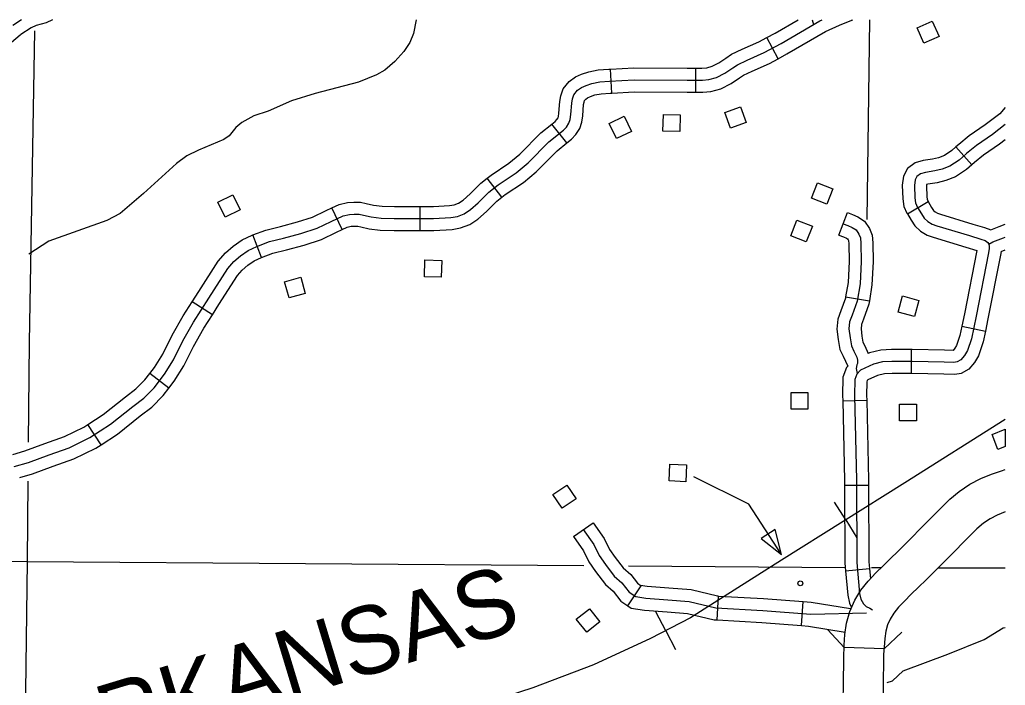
# Model space of a CAD drawing. Extents: x 1370130 to 1380143, y 377636 to 380256.
# Drawn here: x 1378779.4 to 1379037.7, y 378658.4 to 378832.9 of the extents above; entities that cross this region are included whole.
import ezdxf

# ---------------------------------------------------------------- set-up
doc = ezdxf.new("R2010")
doc.units = 0
for name, color, linetype in [('Level 10', 7, 'Continuous'), ('Level 32', 7, 'Continuous'), ('Level 35', 7, 'Continuous'), ('Level 37', 7, 'Continuous'), ('Level 40', 7, 'Continuous'), ('Level 45', 7, 'Continuous'), ('Level 5', 7, 'Continuous'), ('Level 56', 7, 'Continuous')]:
    doc.layers.add(name, color=color, linetype=linetype)

msp = doc.modelspace()

# ---------------------------------------------------------------- linework, layer by layer
at = {"layer": 'Level 10'}
msp.add_line((1379005.93, 378667.96), (1378995.44, 378668.29), dxfattribs=at)
for points in [[(1378995.44, 378668.29), (1378995.46, 378668.91), (1378995.64, 378671.72), (1378996.07, 378674.7), (1378996.92, 378677.76), (1378998.21, 378680.65), (1378999.83, 378683.29), (1379001.73, 378685.71), (1379003.74, 378687.82), (1379005.68, 378689.72), (1379007.61, 378691.6), (1379009.52, 378693.46), (1379011.41, 378695.37), (1379013.33, 378697.28), (1379015.2, 378699.19), (1379017.12, 378701.13), (1379019.05, 378703.09), (1379021.03, 378705.08), (1379023.14, 378707.15), (1379025.58, 378709.23), (1379028.34, 378711.11), (1379031.25, 378712.58), (1379034.07, 378713.7), (1379036.71, 378714.63), (1379037.67, 378714.97)], [(1379037.67, 378703.83), (1379035.58, 378703), (1379033.68, 378702.04), (1379031.96, 378700.88), (1379030.24, 378699.4), (1379028.42, 378697.62), (1379026.51, 378695.7), (1379024.59, 378693.75), (1379022.68, 378691.82), (1379020.78, 378689.88), (1379018.84, 378687.96), (1379016.91, 378686.01), (1379014.94, 378684.08), (1379013.03, 378682.22), (1379011.21, 378680.44), (1379009.67, 378678.83), (1379008.47, 378677.29), (1379007.52, 378675.74), (1379006.82, 378674.19), (1379006.37, 378672.55), (1379006.1, 378670.63), (1379005.95, 378668.4), (1379005.93, 378667.96)], [(1378995.01, 378646.07), (1378995.06, 378649.05), (1378995.1, 378652.05), (1378995.16, 378655.03), (1378995.23, 378657.94), (1378995.29, 378660.75), (1378995.33, 378663.5), (1378995.37, 378666.21), (1378995.44, 378668.29)], [(1379005.51, 378645.9), (1379005.55, 378648.88), (1379005.6, 378651.86), (1379005.66, 378654.8), (1379005.73, 378657.7), (1379005.79, 378660.56), (1379005.83, 378663.34), (1379005.87, 378665.96), (1379005.93, 378667.96)]]:
    msp.add_lwpolyline(points, dxfattribs=at)
at = {"layer": 'Level 32'}
for p, q in [((1378997.44, 378832.8), (1378997.4, 378832.91)), ((1378978.16, 378822.69), (1378975.18, 378828.24)), ((1378934.51, 378813.69), (1378934.19, 378819.98)), ((1378956.52, 378813.93), (1378956.52, 378820.23)), ((1378922.74, 378800.59), (1378918.78, 378805.49)), ((1379024.73, 378799.54), (1379028.94, 378794.85)), ((1378905.75, 378786.38), (1378901.86, 378791.34)), ((1379012.01, 378782.02), (1379017.42, 378785.26)), ((1378863.83, 378777.87), (1378861.16, 378783.58)), ((1378884.35, 378777.66), (1378884.35, 378783.96)), ((1378994.07, 378776.44), (1378996.33, 378782.32)), ((1378842.72, 378770.57), (1378840.48, 378776.46)), ((1378829.86, 378755.55), (1378824.56, 378758.95)), ((1378995.83, 378760.22), (1379002.05, 378759.2)), ((1379026.28, 378752.57), (1379032.44, 378751.26)), ((1379013.01, 378746.44), (1379013.01, 378740.14)), ((1378818.43, 378736.27), (1378813.45, 378740.12)), ((1378995.05, 378732.95), (1379001.35, 378733.1)), ((1378800.7, 378721.46), (1378797.24, 378726.73)), ((1378995.55, 378710.84), (1379001.85, 378710.86)), ((1378924.47, 378697.39), (1378929.62, 378701.01)), ((1378995.79, 378688.4), (1379002.07, 378688.97)), ((1378938.76, 378679.23), (1378942.25, 378684.47)), ((1378962.18, 378675.49), (1378962.52, 378681.78)), ((1378984.23, 378674.04), (1378984.72, 378680.32))]:
    msp.add_line(p, q, dxfattribs=at)
for points in [[(1378777.92, 378715.7), (1378781.69, 378716.82), (1378787.05, 378718.81), (1378792.34, 378720.66), (1378797.76, 378723.31), (1378803.12, 378726.82), (1378809.01, 378731.52), (1378811.92, 378733.7), (1378814.56, 378736.41), (1378817.27, 378739.92), (1378819.66, 378743.69), (1378822.1, 378748.72), (1378824.88, 378753.62), (1378828.91, 378759.9), (1378833.87, 378767.71), (1378835.46, 378769.5), (1378837.25, 378771.02), (1378839.23, 378772.41), (1378841.48, 378773.47), (1378844.79, 378774.73), (1378848.49, 378775.65), (1378853.05, 378776.84), (1378857.29, 378778.23), (1378860.99, 378780.02), (1378864.1, 378781.48), (1378865.75, 378781.87), (1378867.01, 378781.94), (1378868.33, 378781.94), (1378869.46, 378781.68), (1378871.51, 378781.21), (1378874.09, 378780.88), (1378877.53, 378780.81), (1378887.84, 378780.81), (1378892.34, 378781.01), (1378894.06, 378781.34), (1378895.85, 378782.01), (1378897.5, 378783.13), (1378899.55, 378784.92), (1378902.33, 378787.7), (1378904.77, 378789.62), (1378909.47, 378792.73), (1378912.58, 378795.37), (1378918.07, 378800.87), (1378921.84, 378803.91), (1378922.63, 378804.77), (1378923.29, 378805.76), (1378923.62, 378806.76), (1378923.82, 378808.08), (1378924.02, 378811.06), (1378924.22, 378812.12), (1378924.61, 378813.24), (1378925.54, 378814.43), (1378926.6, 378815.16), (1378927.79, 378815.69), (1378929.31, 378816.22), (1378931.36, 378816.62), (1378933.94, 378816.81), (1378940.36, 378817.14), (1378954.31, 378817.08), (1378958.28, 378817.08), (1378960, 378817.21), (1378961.98, 378817.74), (1378964.17, 378818.87), (1378966.22, 378820.25), (1378967.47, 378821.12), (1378969.99, 378822.31), (1378974.48, 378824.29), (1378978.91, 378826.67), (1378989.1, 378832.63), (1378989.71, 378832.91)], [(1378975.18, 378828.24), (1378977.37, 378829.42), (1378983.35, 378832.91)], [(1378978.16, 378822.69), (1378980.45, 378823.93), (1378990.56, 378829.84), (1378994.18, 378831.52), (1378997.44, 378832.8)], [(1378987.03, 378832.91), (1378987.39, 378831.63)], [(1378997.44, 378832.8), (1378997.72, 378832.91)], [(1378956.52, 378820.23), (1378958.16, 378820.23), (1378959.47, 378820.33), (1378960.84, 378820.7), (1378962.55, 378821.58), (1378964.44, 378822.86), (1378965.9, 378823.85), (1378968.67, 378825.17), (1378973.1, 378827.12), (1378975.18, 378828.24)], [(1378956.52, 378813.93), (1378958.4, 378813.93), (1378960.53, 378814.09), (1378963.12, 378814.78), (1378965.78, 378816.15), (1378967.99, 378817.65), (1378969.05, 378818.38), (1378971.3, 378819.44), (1378975.87, 378821.46), (1378978.16, 378822.69)], [(1378918.78, 378805.49), (1378919.68, 378806.22), (1378920.15, 378806.72), (1378920.44, 378807.16), (1378920.55, 378807.49), (1378920.69, 378808.42), (1378920.89, 378811.45), (1378921.17, 378812.93), (1378921.81, 378814.77), (1378923.35, 378816.75), (1378925.05, 378817.92), (1378926.63, 378818.62), (1378928.49, 378819.27), (1378930.94, 378819.74), (1378933.74, 378819.96), (1378934.19, 378819.98)], [(1378934.19, 378819.98), (1378940.28, 378820.3), (1378954.32, 378820.23), (1378956.52, 378820.23)], [(1378922.74, 378800.59), (1378924, 378801.6), (1378925.11, 378802.82), (1378926.15, 378804.37), (1378926.7, 378806.02), (1378926.96, 378807.74), (1378927.15, 378810.66), (1378927.27, 378811.3), (1378927.42, 378811.71), (1378927.73, 378812.11), (1378928.14, 378812.4), (1378928.95, 378812.76), (1378930.13, 378813.17), (1378931.78, 378813.49), (1378934.14, 378813.67), (1378934.51, 378813.69)], [(1378934.51, 378813.69), (1378940.43, 378813.99), (1378954.3, 378813.93), (1378956.52, 378813.93)], [(1379037.67, 378809.9), (1379036.21, 378808.27), (1379032.42, 378805.33), (1379028.22, 378802.46), (1379025.48, 378800.21), (1379024.73, 378799.54)], [(1378901.86, 378791.34), (1378902.93, 378792.17), (1378907.57, 378795.25), (1378910.44, 378797.69), (1378915.96, 378803.21), (1378918.78, 378805.49)], [(1379037.67, 378805.42), (1379034.28, 378802.78), (1379030.11, 378799.94), (1379027.53, 378797.82), (1379025.61, 378796.1), (1379023.17, 378794.51), (1379021.12, 378793.72), (1379019.2, 378793.26), (1379016.75, 378792.86), (1379015.43, 378792.53), (1379014.5, 378791.8), (1379014.04, 378790.94), (1379013.84, 378789.42), (1379013.97, 378786.24), (1379014.17, 378784.85), (1379014.7, 378783.66), (1379015.69, 378782.01), (1379016.42, 378780.88), (1379017.35, 378780.02), (1379018.54, 378779.29), (1379019.73, 378778.9), (1379028.26, 378776.32), (1379031.23, 378775.39), (1379032.36, 378774.99), (1379033.07, 378774.53), (1379033.39, 378774.07), (1379033.48, 378773.4), (1379033.48, 378772.87), (1379033.29, 378771.75), (1379030.04, 378755.14), (1379028.79, 378749.25), (1379027.8, 378746.14), (1379027, 378744.88), (1379026.01, 378743.69), (1379025.08, 378743.16), (1379024.22, 378743.03), (1379021.64, 378743.1), (1379013.25, 378743.29), (1379007.95, 378743.29), (1379005.51, 378743.16), (1379003.13, 378742.57), (1378999.75, 378741.04), (1378998.76, 378739.99), (1378998.23, 378738.6), (1378998.17, 378734.36), (1378998.7, 378712.13), (1378998.76, 378690.55), (1378999.49, 378682.48), (1378999.82, 378680.96), (1379000.48, 378679.7), (1379001.21, 378679.04), (1379002.2, 378678.58), (1379002.85, 378678.17)], [(1378905.75, 378786.38), (1378906.62, 378787.06), (1378911.37, 378790.2), (1378914.72, 378793.06), (1378920.18, 378798.52), (1378922.74, 378800.59)], [(1379037.67, 378801.43), (1379036.13, 378800.24), (1379032, 378797.42), (1379029.58, 378795.43), (1379028.94, 378794.85)], [(1379024.73, 378799.54), (1379023.69, 378798.61), (1379021.72, 378797.33), (1379020.17, 378796.73), (1379018.57, 378796.35), (1379016.12, 378795.95), (1379014.01, 378795.42), (1379012.04, 378793.87), (1379010.99, 378791.92), (1379010.68, 378789.56), (1379010.83, 378785.95), (1379011.11, 378783.97), (1379011.9, 378782.21), (1379012.01, 378782.02)], [(1379028.94, 378794.85), (1379027.53, 378793.59), (1379024.61, 378791.69), (1379022.06, 378790.71), (1379019.82, 378790.17), (1379017.39, 378789.77), (1379017.05, 378789.69), (1379017, 378789.28), (1379017.11, 378786.53), (1379017.23, 378785.73), (1379017.5, 378785.12), (1379017.42, 378785.26)], [(1378884.35, 378783.96), (1378887.77, 378783.96), (1378891.97, 378784.15), (1378893.21, 378784.39), (1378894.39, 378784.83), (1378895.57, 378785.63), (1378897.4, 378787.22), (1378900.23, 378790.06), (1378901.86, 378791.34)], [(1378861.16, 378783.58), (1378863.05, 378784.46), (1378865.3, 378785), (1378866.93, 378785.09), (1378868.7, 378785.09), (1378870.16, 378784.74), (1378872.06, 378784.32), (1378874.32, 378784.03), (1378877.56, 378783.96), (1378884.35, 378783.96)], [(1378884.35, 378777.66), (1378887.91, 378777.66), (1378892.71, 378777.88), (1378894.91, 378778.3), (1378897.3, 378779.19), (1378899.43, 378780.63), (1378901.7, 378782.61), (1378904.42, 378785.34), (1378905.75, 378786.38)], [(1379017.42, 378785.26), (1379018.37, 378783.67), (1379018.85, 378782.92), (1379019.26, 378782.54), (1379019.87, 378782.17), (1379020.68, 378781.9), (1379029.18, 378779.33), (1379032.23, 378778.38), (1379033.84, 378777.81)], [(1378840.48, 378776.46), (1378843.84, 378777.74), (1378847.71, 378778.71), (1378852.16, 378779.87), (1378856.11, 378781.16), (1378859.64, 378782.87), (1378861.16, 378783.58)], [(1378996.33, 378782.32), (1378997.58, 378781.84), (1378999, 378781.25), (1379000.81, 378780.09), (1379002.11, 378778.14), (1379002.79, 378776.43), (1379002.92, 378774.37), (1379003.02, 378769.43), (1379002.73, 378763.35), (1379002.05, 378759.2)], [(1379012.01, 378782.02), (1379013.02, 378780.34), (1379013.99, 378778.84), (1379015.43, 378777.5), (1379017.2, 378776.42), (1379018.77, 378775.89), (1379027.33, 378773.3), (1379030.2, 378772.41)], [(1378995.2, 378779.38), (1378996.41, 378778.91), (1378997.53, 378778.44), (1378998.56, 378777.79), (1378999.31, 378776.67), (1378999.68, 378775.73), (1378999.77, 378774.24), (1378999.87, 378769.47), (1378999.59, 378763.68), (1378998.84, 378759.1), (1378997.53, 378755.46), (1378996.88, 378753.68), (1378996.69, 378751.81), (1378996.97, 378749.48), (1378997.35, 378747.42), (1378998, 378746.02), (1378998.75, 378744.43), (1378998.93, 378743.59), (1378998.93, 378742.75), (1378998.75, 378742.38), (1378998.56, 378741.44), (1378998.87, 378740.1)], [(1379033.84, 378777.81), (1379036.09, 378778.7), (1379037.67, 378779.27)], [(1378842.72, 378770.57), (1378845.73, 378771.72), (1378849.27, 378772.6), (1378853.94, 378773.82), (1378858.47, 378775.31), (1378862.34, 378777.18), (1378863.83, 378777.87)], [(1378863.83, 378777.87), (1378865.15, 378778.49), (1378866.21, 378778.74), (1378867.09, 378778.79), (1378867.97, 378778.79), (1378868.75, 378778.61), (1378870.96, 378778.11), (1378873.85, 378777.74), (1378877.49, 378777.66), (1378884.35, 378777.66)], [(1378824.56, 378758.95), (1378826.26, 378761.6), (1378831.35, 378769.62), (1378833.25, 378771.75), (1378835.32, 378773.52), (1378837.65, 378775.15), (1378840.25, 378776.37), (1378840.48, 378776.46)], [(1378994.07, 378776.44), (1378995.24, 378775.99), (1378996.07, 378775.64), (1378996.31, 378775.49), (1378996.5, 378775.19), (1378996.57, 378775.03), (1378996.63, 378774.11), (1378996.72, 378769.52), (1378996.45, 378764.01), (1378995.83, 378760.22)], [(1379033.39, 378774.07), (1379034.42, 378774.66), (1379037.2, 378775.75), (1379037.67, 378775.92)], [(1379030.2, 378772.41), (1379026.96, 378755.77), (1379026.28, 378752.57)], [(1379036.55, 378772.11), (1379036.38, 378771.17), (1379033.13, 378754.51), (1379032.44, 378751.26)], [(1379036.55, 378772.11), (1379037.67, 378772.55)], [(1378829.86, 378755.55), (1378831.57, 378758.21), (1378836.4, 378765.81), (1378837.67, 378767.24), (1378839.18, 378768.53), (1378840.82, 378769.68), (1378842.71, 378770.57), (1378842.72, 378770.57)], [(1378813.45, 378740.12), (1378814.69, 378741.73), (1378816.9, 378745.23), (1378819.31, 378750.19), (1378822.18, 378755.25), (1378824.56, 378758.95)], [(1378995.83, 378760.22), (1378995.78, 378759.89), (1378994.57, 378756.53), (1378993.79, 378754.4), (1378993.52, 378751.78), (1378993.86, 378749.01), (1378994.32, 378746.46), (1378995.15, 378744.68), (1378996.38, 378742.06)], [(1379002.05, 378759.2), (1379001.9, 378758.31), (1379000.49, 378754.38), (1378999.97, 378752.97), (1378999.86, 378751.85), (1379000.09, 378749.95), (1379000.37, 378748.39), (1379000.85, 378747.36), (1379001.77, 378745.41)], [(1378818.43, 378736.27), (1378819.86, 378738.11), (1378822.41, 378742.16), (1378824.89, 378747.25), (1378827.58, 378751.99), (1378829.86, 378755.55)], [(1379026.28, 378752.57), (1379025.74, 378750.06), (1379024.92, 378747.48), (1379024.45, 378746.74), (1379023.99, 378746.19), (1379021.72, 378746.24), (1379013.28, 378746.44), (1379013.01, 378746.44)], [(1379032.44, 378751.26), (1379031.84, 378748.44), (1379030.67, 378744.8), (1379029.56, 378743.03), (1379028.07, 378741.24), (1379026.14, 378740.14), (1379024.43, 378739.87), (1379021.57, 378739.95), (1379013.21, 378740.14), (1379013.01, 378740.14)], [(1379013.01, 378746.44), (1379007.87, 378746.44), (1379005.04, 378746.29), (1379002.09, 378745.55), (1379001.77, 378745.41)], [(1378996.38, 378742.06), (1378996.04, 378741.69), (1378995.09, 378739.2), (1378995.02, 378734.35), (1378995.05, 378732.95)], [(1378797.24, 378726.73), (1378801.27, 378729.37), (1378807.08, 378734.01), (1378809.83, 378736.07), (1378812.18, 378738.48), (1378813.45, 378740.12)], [(1379013.01, 378740.14), (1379008.04, 378740.14), (1379005.98, 378740.03), (1379004.16, 378739.58), (1379001.62, 378738.43), (1379001.48, 378738.28), (1379001.37, 378737.99), (1379001.32, 378734.37), (1379001.35, 378733.1)], [(1378800.7, 378721.46), (1378804.97, 378724.26), (1378810.94, 378729.02), (1378814, 378731.33), (1378816.94, 378734.34), (1378818.43, 378736.27)], [(1378995.05, 378732.95), (1378995.55, 378712.08), (1378995.55, 378710.84)], [(1379001.35, 378733.1), (1379001.85, 378712.17), (1379001.85, 378710.86)], [(1378777.55, 378718.88), (1378780.69, 378719.81), (1378785.98, 378721.77), (1378791.12, 378723.57), (1378796.2, 378726.05), (1378797.24, 378726.73)], [(1378779.35, 378712.84), (1378782.69, 378713.84), (1378788.12, 378715.85), (1378793.56, 378717.75), (1378799.32, 378720.57), (1378800.7, 378721.46)], [(1378995.55, 378710.84), (1378995.61, 378690.41), (1378995.79, 378688.4)], [(1379001.85, 378710.86), (1379001.91, 378690.7), (1379002.07, 378688.97)], [(1378927.04, 378699.2), (1378929.8, 378695.28), (1378931.25, 378692.37), (1378932.85, 378690.05), (1378935.17, 378687), (1378937.21, 378685.26), (1378939.09, 378682.79), (1378940.84, 378681.63), (1378943.45, 378681.19), (1378949.26, 378680.75), (1378954.85, 378680.32), (1378961.82, 378678.66), (1378974.11, 378678), (1378986.73, 378677), (1379001.33, 378677.33)], [(1378929.62, 378701.01), (1378932.52, 378696.9), (1378933.97, 378693.98), (1378935.4, 378691.9), (1378937.48, 378689.17), (1378939.51, 378687.43), (1378941.28, 378685.12), (1378942.25, 378684.47)], [(1378924.47, 378697.39), (1378927.09, 378693.66), (1378928.53, 378690.77), (1378930.3, 378688.2), (1378932.87, 378684.83), (1378934.91, 378683.08), (1378936.91, 378680.46), (1378938.76, 378679.23)], [(1379002.07, 378688.97), (1379002.31, 378686.32)], [(1378995.79, 378688.4), (1378996.37, 378682), (1378996.83, 378679.87), (1378997.39, 378678.81)], [(1378942.02, 378684.62), (1378943.83, 378684.32), (1378949.49, 378683.89), (1378955.34, 378683.45), (1378962.28, 378681.79), (1378962.52, 378681.78)], [(1378962.52, 378681.78), (1378974.32, 378681.14), (1378984.72, 378680.32)], [(1378938.76, 378679.23), (1378939.65, 378678.63), (1378943.07, 378678.06), (1378949.02, 378677.61), (1378954.36, 378677.2), (1378961.37, 378675.53), (1378962.18, 378675.49)], [(1378984.72, 378680.32), (1378986.81, 378680.16), (1378997.12, 378678.5)], [(1378962.18, 378675.49), (1378973.9, 378674.86), (1378984.23, 378674.04)], [(1378984.23, 378674.04), (1378986.07, 378673.89), (1378995.73, 378672.34)]]:
    msp.add_lwpolyline(points, dxfattribs=at)
at = {"layer": 'Level 35'}
for points in [[(1378883.25, 378832.91), (1378882.53, 378829.28), (1378881.56, 378826.94), (1378880.01, 378824.57), (1378877.63, 378821.92), (1378875.03, 378819.68), (1378872.85, 378818.43), (1378868.18, 378816.53), (1378856.8, 378813.52), (1378850.57, 378811.66), (1378844.51, 378808.96), (1378840.74, 378807.69), (1378837.57, 378805.93), (1378836.02, 378804.66), (1378834.21, 378802.49), (1378832.87, 378801.48), (1378826.17, 378798.71), (1378823.12, 378797.22), (1378820.47, 378795.23), (1378811.78, 378787.35), (1378805.67, 378782.13)], [(1378805.67, 378782.13), (1378802.18, 378780.24), (1378787.02, 378774.86), (1378781.78, 378771.43)], [(1379006.72, 378659.13), (1379008.14, 378659.52), (1379010.87, 378662.15), (1379022.57, 378666.49), (1379032.1, 378670.39), (1379037.08, 378673.42), (1379037.67, 378673.56)]]:
    msp.add_lwpolyline(points, dxfattribs=at)
at = {"layer": 'Level 37'}
for points in [[(1378995.44, 378668.29), (1378991.13, 378672.89)], [(1379010.53, 378672.27), (1379005.93, 378667.96)]]:
    msp.add_lwpolyline(points, dxfattribs=at)
at = {"layer": 'Level 40'}
for p, q in [((1378995.86, 378701.73), (1378992.92, 378706.43)), ((1378995.86, 378701.73), (1378998.8, 378697.03)), ((1378948.67, 378672.68), (1378946.12, 378677.61)), ((1378948.67, 378672.68), (1378951.22, 378667.76))]:
    msp.add_line(p, q, dxfattribs=at)
msp.add_lwpolyline([(1379037.67, 378728.08), (1379011.37, 378711.43), (1378979.03, 378691.2), (1378955.14, 378676.03), (1378944.66, 378670.61), (1378929.78, 378663.71), (1378913.88, 378657.74), (1378900.65, 378653.42), (1378885.95, 378648.73), (1378808.4, 378625.74), (1378735.63, 378603.5), (1378725.52, 378599.73), (1378717.44, 378595.87), (1378710.36, 378591.91), (1378703.75, 378587.87), (1378696.49, 378582.17), (1378688.4, 378574.44), (1378681.14, 378566.81), (1378672.78, 378556.79), (1378636.31, 378509.63), (1378616.64, 378482.33), (1378598.45, 378460.26)], dxfattribs=at)
msp.add_lwpolyline([(1379037.67, 378728.08), (1379011.37, 378711.43), (1378979.03, 378691.2), (1378955.14, 378676.03), (1378944.66, 378670.61), (1378929.78, 378663.71), (1378913.88, 378657.74), (1378900.65, 378653.42), (1378885.95, 378648.73), (1378808.4, 378625.74), (1378735.63, 378603.5), (1378725.52, 378599.73), (1378717.44, 378595.87), (1378710.36, 378591.91), (1378703.75, 378587.87), (1378696.49, 378582.17), (1378688.4, 378574.44), (1378681.14, 378566.81), (1378672.78, 378556.79), (1378636.31, 378509.63), (1378616.64, 378482.33), (1378598.45, 378460.26)], dxfattribs=at)
at = {"layer": 'Level 45'}
for points in [[(1378779.86, 378832.91), (1378777.52, 378831.37)], [(1378787.91, 378832.91), (1378786.32, 378832.1), (1378783.69, 378831.4), (1378782.36, 378830.79), (1378779.62, 378828.99)], [(1378779.62, 378828.99), (1378779.44, 378828.86), (1378777.24, 378826.92), (1378776.05, 378826.44), (1378774.59, 378825.27), (1378773.9, 378824.57), (1378772.27, 378823.29), (1378770.69, 378822.77), (1378769.23, 378822.44), (1378767.22, 378822.82), (1378766, 378823.18), (1378765.68, 378823.18), (1378765.2, 378822.79), (1378763.92, 378821.51), (1378761.93, 378820.28), (1378761.43, 378819.81)]]:
    msp.add_lwpolyline(points, dxfattribs=at)
at = {"layer": 'Level 5'}
for points in [[(1379002.11, 378832.84), (1379001.4, 378780.52)], [(1378783.21, 378829.97), (1378781.87, 378748.25), (1378781.6, 378722.09)], [(1378781.49, 378711.87), (1378781.27, 378690.81)], [(1378675.69, 378693), (1378781.27, 378690.81)], [(1378781.27, 378690.81), (1378779.49, 378547.81)], [(1378781.27, 378690.81), (1378927.19, 378689.78)], [(1378938.89, 378689.7), (1378995.71, 378689.29)], [(1379002.58, 378689.25), (1379005.2, 378689.25)], [(1379020.09, 378689.2), (1379037.67, 378689.14)]]:
    msp.add_lwpolyline(points, dxfattribs=at)
at = {"layer": 'Level 56'}
for p, q in [((1379034.2, 378724.13), (1379037.67, 378725.51)), ((1379037.67, 378725.51), (1379037.67, 378720.99)), ((1379035.75, 378720.23), (1379034.2, 378724.13)), ((1379037.67, 378720.99), (1379035.75, 378720.23))]:
    msp.add_line(p, q, dxfattribs=at)
for points in [[(1379018.53, 378832.55), (1379020.3, 378828.55), (1379016.29, 378826.77), (1379014.53, 378830.77)], [(1378937.81, 378807.58), (1378939.69, 378803.63), (1378935.74, 378801.74), (1378933.85, 378805.69)], [(1378952.43, 378807.93), (1378952.33, 378803.56), (1378947.95, 378803.66), (1378948.05, 378808.04)], [(1378968.26, 378810.05), (1378969.77, 378805.95), (1378965.66, 378804.43), (1378964.15, 378808.54)], [(1378988.42, 378790.17), (1378992.5, 378788.6), (1378990.93, 378784.51), (1378986.85, 378786.08)], [(1378835.19, 378786.99), (1378837.14, 378783.07), (1378833.21, 378781.12), (1378831.27, 378785.04)], [(1378983.02, 378780.32), (1378987.1, 378778.75), (1378985.52, 378774.66), (1378981.44, 378776.23)], [(1378889.95, 378769.79), (1378889.84, 378765.42), (1378885.46, 378765.52), (1378885.56, 378769.9)], [(1378853.01, 378765.37), (1378854.17, 378761.15), (1378849.94, 378759.99), (1378848.78, 378764.21)], [(1379014.97, 378759.31), (1379013.83, 378755.09), (1379009.6, 378756.25), (1379010.74, 378760.46)], [(1378981.55, 378730.81), (1378981.55, 378735.18), (1378985.93, 378735.18), (1378985.93, 378730.81)], [(1379009.97, 378727.75), (1379009.97, 378732.12), (1379014.36, 378732.12), (1379014.36, 378727.75)], [(1378949.75, 378716.36), (1378954.12, 378716.14), (1378953.9, 378711.76), (1378949.54, 378711.98)], [(1378922.75, 378710.87), (1378925.17, 378707.23), (1378921.53, 378704.8), (1378919.1, 378708.43)], [(1378977.32, 378699.22), (1378973.72, 378696.89), (1378979.02, 378692.67)], [(1378928.67, 378678.43), (1378931.4, 378675.01), (1378927.98, 378672.27), (1378925.24, 378675.69)]]:
    msp.add_lwpolyline(points, close=True, dxfattribs=at)
msp.add_lwpolyline([(1378979.02, 378692.67), (1378970.45, 378705.88), (1378956.08, 378713)], dxfattribs=at)
msp.add_circle((1378983.95, 378685.11), 0.63, dxfattribs=at)

# ---------------------------------------------------------------- texts
at = {"layer": 'Level 40'}
msp.add_text('ARKANSAS', height=17.741, rotation=16.8546, dxfattribs=at).set_placement((1378787.75, 378635.84))

doc.saveas('drawing.dxf')
